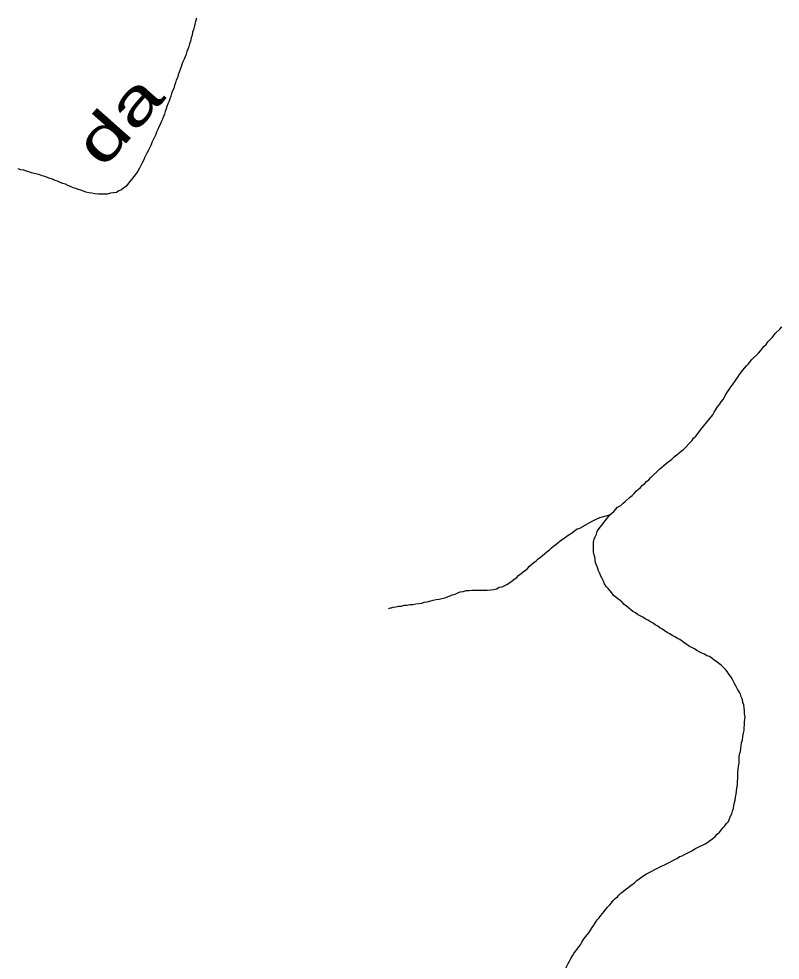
# Model space of a CAD drawing. Extents: x 652.3 to 678, y 7316.9 to 7344.9.
# Drawn here: x 654.325 to 655.74, y 7337.715 to 7339.464 of the extents above; entities that cross this region are included whole.
import ezdxf
from ezdxf.enums import TextEntityAlignment as Align

# ---------------------------------------------------------------- set-up
doc = ezdxf.new("R2010")
doc.units = 0
doc.header["$LTSCALE"] = 0.032
doc.layers.add('61', color=7, linetype='Continuous')
doc.layers.add('7', color=7, linetype='Continuous', lineweight=25)

msp = doc.modelspace()

# ---------------------------------------------------------------- linework, layer by layer
at = {"layer": '7'}
for points in [[(654.6553, 7339.4652), (654.6538, 7339.4589), (654.6522, 7339.4541), (654.6514, 7339.4485), (654.6498, 7339.4437), (654.6482, 7339.439), (654.6474, 7339.4334), (654.6458, 7339.4286), (654.6442, 7339.4223), (654.6426, 7339.4175), (654.641, 7339.4127), (654.6394, 7339.4079), (654.6378, 7339.4032), (654.6362, 7339.3984), (654.6347, 7339.3936), (654.6323, 7339.3888), (654.6299, 7339.3841)], [(654.6299, 7339.3841), (654.6283, 7339.3793), (654.6267, 7339.3745), (654.6251, 7339.3697), (654.6235, 7339.365), (654.6211, 7339.3602), (654.6203, 7339.3546), (654.6179, 7339.3498), (654.6164, 7339.3451), (654.6148, 7339.3403), (654.6132, 7339.3347), (654.6108, 7339.33), (654.6092, 7339.3252), (654.6076, 7339.3204), (654.606, 7339.3156), (654.6044, 7339.3109), (654.602, 7339.3061), (654.6004, 7339.3013), (654.5989, 7339.2965), (654.5973, 7339.2918), (654.5957, 7339.287), (654.5941, 7339.2822), (654.5925, 7339.2774), (654.5901, 7339.2727), (654.5877, 7339.2679), (654.5853, 7339.2631), (654.5837, 7339.2583), (654.5813, 7339.2536), (654.5798, 7339.2488), (654.5774, 7339.244), (654.575, 7339.2392), (654.5726, 7339.2345), (654.571, 7339.2297), (654.5686, 7339.2249), (654.5662, 7339.2201), (654.5638, 7339.2154), (654.5615, 7339.2106), (654.5591, 7339.2058), (654.5567, 7339.201), (654.5543, 7339.1963), (654.5519, 7339.1915), (654.5495, 7339.1867), (654.5471, 7339.182), (654.5439, 7339.1772), (654.5408, 7339.1732), (654.5376, 7339.1692), (654.5344, 7339.1652), (654.5312, 7339.1613), (654.528, 7339.1565), (654.5241, 7339.1525), (654.5201, 7339.1493), (654.5161, 7339.1461), (654.5113, 7339.1446), (654.5066, 7339.1414), (654.501, 7339.1406), (654.4954, 7339.1398), (654.4898, 7339.1382), (654.4843, 7339.1382), (654.4787, 7339.1382), (654.4731, 7339.1382), (654.4668, 7339.139), (654.4612, 7339.1398), (654.4556, 7339.1406), (654.4501, 7339.1422), (654.4453, 7339.1438), (654.4405, 7339.1454), (654.4357, 7339.1469), (654.431, 7339.1485), (654.4262, 7339.1501), (654.4214, 7339.1525), (654.4166, 7339.1541), (654.4119, 7339.1565), (654.4071, 7339.1581), (654.4023, 7339.1597), (654.3975, 7339.1621), (654.3928, 7339.1637), (654.388, 7339.166), (654.3832, 7339.1676), (654.3784, 7339.1692), (654.3737, 7339.1708), (654.3689, 7339.1724), (654.3641, 7339.174), (654.3594, 7339.1756), (654.3538, 7339.1764), (654.349, 7339.178), (654.3442, 7339.1796), (654.3395, 7339.1812), (654.3347, 7339.1827), (654.3291, 7339.1835), (654.3243, 7339.1851)], [(655.4311, 7338.5486), (655.4375, 7338.5565), (655.4439, 7338.5597), (655.4479, 7338.5637), (655.4518, 7338.5669), (655.4598, 7338.5748), (655.4646, 7338.578), (655.4685, 7338.582), (655.4725, 7338.586), (655.4765, 7338.59), (655.4805, 7338.5931), (655.4837, 7338.5971), (655.4884, 7338.6003), (655.4916, 7338.6043), (655.4956, 7338.6075), (655.4996, 7338.6114), (655.5155, 7338.6274), (655.5195, 7338.6305), (655.5234, 7338.6337), (655.5274, 7338.6369), (655.5314, 7338.6401), (655.5354, 7338.6433), (655.5394, 7338.6465), (655.5433, 7338.6504), (655.5481, 7338.6536), (655.5521, 7338.6576), (655.5561, 7338.6608), (655.56, 7338.664), (655.576, 7338.6799), (655.5791, 7338.6846), (655.5831, 7338.6886), (655.5895, 7338.6966), (655.5927, 7338.7006), (655.6149, 7338.7284), (655.6173, 7338.7332), (655.6237, 7338.7427), (655.6269, 7338.7475), (655.6301, 7338.7523), (655.634, 7338.7563), (655.6388, 7338.7658), (655.642, 7338.7706), (655.6452, 7338.7754), (655.6484, 7338.7801), (655.6515, 7338.7841), (655.6579, 7338.7937), (655.6611, 7338.7984), (655.6643, 7338.8032), (655.6706, 7338.8112), (655.6738, 7338.8151), (655.677, 7338.8191), (655.681, 7338.8231), (655.6874, 7338.8311), (655.6993, 7338.843), (655.7033, 7338.847), (655.7096, 7338.8549), (655.7136, 7338.8589), (655.7168, 7338.8637), (655.7248, 7338.8716), (655.7311, 7338.8796), (655.7391, 7338.8875), (655.7431, 7338.8915)], [(655.3906, 7338.5303), (655.3977, 7338.5343), (655.4049, 7338.5374), (655.4232, 7338.5422)], [(655.4016, 7338.5141), (655.4144, 7338.5311), (655.4232, 7338.5422), (655.4311, 7338.5486)], [(655.012, 7338.3682), (655.0128, 7338.3684), (655.0143, 7338.3688), (655.0158, 7338.3692), (655.0174, 7338.3696), (655.0206, 7338.3704), (655.0261, 7338.3711), (655.0309, 7338.3727), (655.0365, 7338.3727), (655.0413, 7338.3743), (655.0468, 7338.3743), (655.0516, 7338.3759), (655.0572, 7338.3759), (655.0627, 7338.3767), (655.0683, 7338.3775), (655.0739, 7338.3783), (655.0787, 7338.3799), (655.0842, 7338.3807), (655.0906, 7338.3823), (655.0954, 7338.3839), (655.1009, 7338.3847), (655.1065, 7338.3855), (655.1113, 7338.3871), (655.1168, 7338.3879), (655.1216, 7338.3902), (655.1264, 7338.3918), (655.1312, 7338.3934), (655.1359, 7338.395), (655.1407, 7338.3974), (655.1455, 7338.399), (655.1511, 7338.3998), (655.1566, 7338.4014), (655.1622, 7338.4014), (655.1678, 7338.4022), (655.1733, 7338.4022), (655.1789, 7338.4022), (655.1845, 7338.4022), (655.19, 7338.4022), (655.1956, 7338.4022), (655.202, 7338.403), (655.2076, 7338.4038), (655.2131, 7338.4046), (655.2179, 7338.4077), (655.2235, 7338.4085), (655.2282, 7338.4109), (655.233, 7338.4133), (655.2378, 7338.4165), (655.2418, 7338.4197), (655.2457, 7338.4229), (655.2505, 7338.426), (655.2545, 7338.43), (655.2585, 7338.4332), (655.2625, 7338.4364), (655.2664, 7338.4396), (655.2704, 7338.4428), (655.2744, 7338.4467), (655.2784, 7338.4507), (655.2823, 7338.4539), (655.2863, 7338.4571), (655.2903, 7338.4603), (655.2943, 7338.4634), (655.2983, 7338.4666), (655.3022, 7338.4698), (655.3062, 7338.4738), (655.311, 7338.477), (655.315, 7338.481), (655.319, 7338.4841), (655.3229, 7338.4873), (655.3269, 7338.4905), (655.3309, 7338.4937), (655.3357, 7338.4969), (655.3404, 7338.5), (655.3444, 7338.5032), (655.3492, 7338.5064), (655.354, 7338.5096), (655.3579, 7338.5128), (655.3627, 7338.516), (655.3675, 7338.5176), (655.3906, 7338.5303)], [(655.6683, 7338.1189), (655.6698, 7338.1237), (655.6706, 7338.1308), (655.6714, 7338.1364), (655.673, 7338.1412), (655.673, 7338.1468), (655.6738, 7338.1523), (655.6738, 7338.1579), (655.6746, 7338.1667), (655.6738, 7338.1722), (655.6738, 7338.1778), (655.673, 7338.1834), (655.6722, 7338.1889), (655.6706, 7338.1937), (655.6698, 7338.1993), (655.6675, 7338.2041), (655.6659, 7338.2088), (655.6635, 7338.2136), (655.6603, 7338.2184), (655.6579, 7338.2231), (655.6555, 7338.2279), (655.6531, 7338.2327), (655.6508, 7338.2375), (655.6476, 7338.2422), (655.6444, 7338.2462), (655.6412, 7338.251), (655.638, 7338.255), (655.634, 7338.259), (655.6301, 7338.2629), (655.6261, 7338.2661), (655.6221, 7338.2693), (655.6173, 7338.2725), (655.6126, 7338.2757), (655.6086, 7338.2788), (655.6038, 7338.2804), (655.599, 7338.2836), (655.5943, 7338.2852), (655.5895, 7338.2876), (655.5847, 7338.29), (655.5807, 7338.2932), (655.576, 7338.2956), (655.5712, 7338.2979), (655.5664, 7338.3011), (655.5616, 7338.3043), (655.5577, 7338.3075), (655.5537, 7338.3107), (655.5489, 7338.3123), (655.5441, 7338.3154), (655.5394, 7338.3178), (655.5346, 7338.321), (655.5298, 7338.3234), (655.525, 7338.3266), (655.5211, 7338.3298), (655.5163, 7338.3322), (655.5123, 7338.3353), (655.5075, 7338.3377), (655.5036, 7338.3409), (655.4988, 7338.3433), (655.494, 7338.3465), (655.4892, 7338.3489), (655.4845, 7338.352), (655.4797, 7338.3544), (655.4749, 7338.3568), (655.4709, 7338.36), (655.4662, 7338.3624), (655.4622, 7338.3656), (655.4582, 7338.3696), (655.4542, 7338.3727), (655.4502, 7338.3759), (655.4463, 7338.3799), (655.4423, 7338.3831), (655.4383, 7338.3863), (655.4343, 7338.3894), (655.4303, 7338.3926), (655.4272, 7338.3974), (655.4232, 7338.4014), (655.42, 7338.4054), (655.4168, 7338.4093), (655.4136, 7338.4141), (655.4113, 7338.4189), (655.4089, 7338.4237), (655.4065, 7338.4284), (655.4049, 7338.4332), (655.4025, 7338.438), (655.4009, 7338.4428), (655.3993, 7338.4475), (655.3969, 7338.4531), (655.3961, 7338.4587), (655.3953, 7338.4642), (655.3937, 7338.469), (655.3929, 7338.4746), (655.3929, 7338.4802), (655.3929, 7338.4857), (655.3929, 7338.4913), (655.3945, 7338.4969), (655.3961, 7338.5016), (655.3985, 7338.5064), (655.4001, 7338.5112), (655.4016, 7338.5141)], [(655.354, 7337.7227), (655.3563, 7337.7274), (655.3595, 7337.7314), (655.3627, 7337.7354), (655.3659, 7337.7394), (655.3691, 7337.7433), (655.3715, 7337.7481), (655.3746, 7337.7529), (655.3778, 7337.7577), (655.381, 7337.7616), (655.3842, 7337.7656), (655.3874, 7337.7704), (655.3906, 7337.7752), (655.3937, 7337.7799), (655.3969, 7337.7847), (655.4001, 7337.7895), (655.4033, 7337.7935), (655.4065, 7337.7975), (655.4097, 7337.8014), (655.4128, 7337.8054), (655.416, 7337.8094), (655.4192, 7337.8134), (655.4232, 7337.8173), (655.4264, 7337.8213), (655.4296, 7337.8253), (655.4335, 7337.8293), (655.4375, 7337.8325), (655.4407, 7337.8364), (655.4447, 7337.8396), (655.4486, 7337.8428), (655.4526, 7337.846), (655.4566, 7337.8492), (655.4606, 7337.8524), (655.4646, 7337.8555), (655.4693, 7337.8587), (655.4733, 7337.8627), (655.4781, 7337.8659), (655.4821, 7337.8691), (655.4868, 7337.8722), (655.4916, 7337.8754), (655.4964, 7337.8778), (655.5012, 7337.8802), (655.5059, 7337.8826), (655.5107, 7337.885), (655.5155, 7337.8874), (655.5203, 7337.8898), (655.525, 7337.8921), (655.5298, 7337.8945), (655.5346, 7337.8969), (655.5394, 7337.8993), (655.5441, 7337.9017), (655.5489, 7337.9041), (655.5529, 7337.9073), (655.5577, 7337.9089), (655.5624, 7337.9112), (655.5672, 7337.9136), (655.572, 7337.916), (655.5768, 7337.9184), (655.5815, 7337.9216), (655.5863, 7337.924), (655.5911, 7337.9264), (655.5958, 7337.9287), (655.6006, 7337.9311), (655.6054, 7337.9343), (655.6102, 7337.9375), (655.6149, 7337.9407), (655.6189, 7337.9447), (655.6229, 7337.9486), (655.6269, 7337.9526), (655.6301, 7337.9566), (655.6332, 7337.9606), (655.6372, 7337.9645), (655.6404, 7337.9685), (655.6436, 7337.9725), (655.646, 7337.9773), (655.6476, 7337.9821), (655.65, 7337.9868), (655.6515, 7337.9916), (655.6531, 7337.9964), (655.6539, 7338.0019), (655.6547, 7338.0075), (655.6563, 7338.0123), (655.6571, 7338.0179), (655.6579, 7338.0234), (655.6587, 7338.029), (655.6595, 7338.0346), (655.6603, 7338.0409), (655.6603, 7338.0465), (655.6611, 7338.0521), (655.6611, 7338.0576), (655.6611, 7338.0632), (655.6619, 7338.0688), (655.6627, 7338.0752), (655.6635, 7338.0807), (655.6635, 7338.0863), (655.6635, 7338.0919), (655.6643, 7338.0974), (655.6659, 7338.1022), (655.6667, 7338.1078), (655.6675, 7338.1133), (655.6683, 7338.1189)], [(655.2943, 7337.6391), (655.3022, 7337.6479), (655.3062, 7337.6518), (655.311, 7337.655), (655.3142, 7337.659), (655.3174, 7337.663), (655.3205, 7337.667), (655.3237, 7337.6717), (655.3269, 7337.6757), (655.3293, 7337.6805), (655.3325, 7337.6845), (655.3349, 7337.6892), (655.338, 7337.694), (655.3412, 7337.6988), (655.3436, 7337.7036), (655.346, 7337.7083), (655.3484, 7337.7131), (655.3508, 7337.7179), (655.354, 7337.7227)]]:
    msp.add_lwpolyline(points, dxfattribs=at)

# ---------------------------------------------------------------- texts
at = {"layer": '61', "width": 1.5}
msp.add_text('da', height=0.08, rotation=48.396, dxfattribs=at).set_placement((654.5407, 7339.2504), align=Align.CENTER)

doc.saveas('drawing.dxf')
